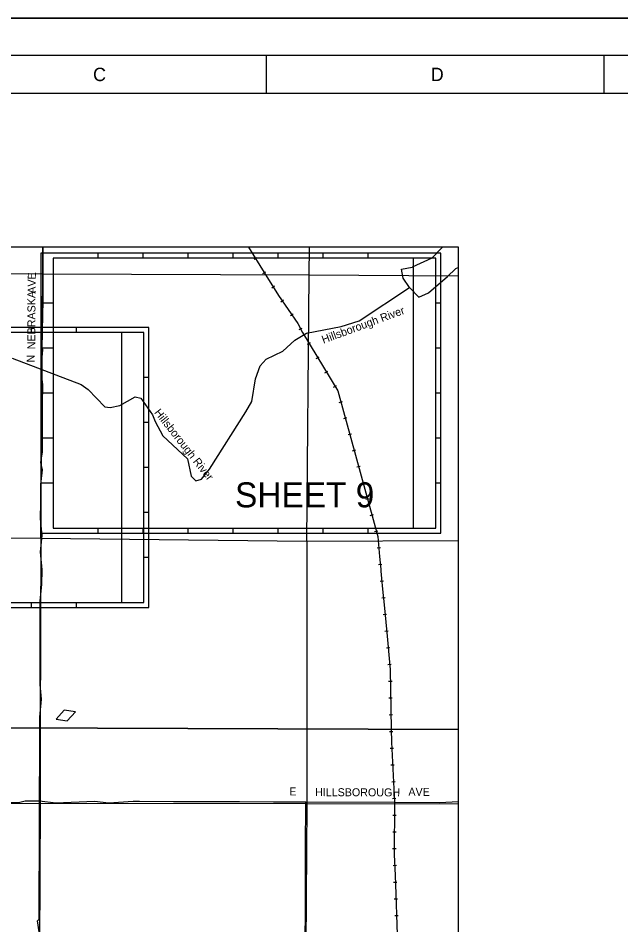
# Model space of a CAD drawing. Extents: x 492225 to 553725, y 1303773 to 1347273.
# Drawn here: x 510130 to 522187, y 1329150 to 1347273 of the extents above; entities that cross this region are included whole.
import ezdxf

# ---------------------------------------------------------------- set-up
doc = ezdxf.new("R2010")
doc.units = 0
for name, color, linetype in [('G-ANNO-TTLB', 7, 'Continuous'), ('Level 1', 7, 'Continuous'), ('Level 13', 7, 'Continuous'), ('Level 19', 7, 'Continuous'), ('Level 22', 7, 'Continuous'), ('Level 37', 7, 'Continuous'), ('Level 41', 7, 'Continuous'), ('Level 5', 7, 'Continuous'), ('Level 52', 7, 'Continuous'), ('Level 63', 7, 'Continuous')]:
    doc.layers.add(name, color=color, linetype=linetype)

msp = doc.modelspace()

# ---------------------------------------------------------------- linework, layer by layer
at = {"layer": 'G-ANNO-TTLB'}
for p, q in [((552975.069, 1346522.564), (492975.069, 1346522.564)), ((515100.069, 1345772.564), (515100.069, 1346522.564)), ((521850.069, 1345772.564), (521850.069, 1346522.564)), ((494850.069, 1345772.564), (552225.069, 1345772.564))]:
    msp.add_line(p, q, dxfattribs=at)
for points in [[(492225.069, 1303772.564), (553725.069, 1303772.564), (553725.069, 1347272.564), (492225.069, 1347272.564)], [(492225.069, 1303772.564), (553725.069, 1303772.564), (553725.069, 1347272.564), (492225.069, 1347272.564)], [(492225.069, 1347272.564), (553725.069, 1347272.564), (553725.069, 1303772.564), (492225.069, 1303772.564)]]:
    msp.add_lwpolyline(points, close=True, dxfattribs=at)
at = {"layer": 'Level 1'}
for p, q in [((510624.879, 1342164.808), (510624.2744, 1342691.84)), ((511733.225, 1342476.88), (511733.225, 1342576.88)), ((512633.225, 1342476.88), (512633.225, 1342576.88)), ((513533.225, 1342476.88), (513533.225, 1342576.88)), ((514433.225, 1342476.88), (514433.225, 1342576.88)), ((515333.225, 1342476.88), (515333.225, 1342576.88)), ((515954.774, 1342144.304), (515956.0062, 1342691.84)), ((516233.225, 1342476.88), (516233.225, 1342576.88)), ((517133.225, 1342476.88), (517133.225, 1342576.88)), ((518033.225, 1342476.88), (518033.225, 1337076.88)), ((505297.021, 1342191.301), (510624.879, 1342164.808)), ((510580.913, 1336869.862), (510624.879, 1342164.808)), ((510624.879, 1342164.808), (515954.774, 1342144.304)), ((515908.569, 1336811.383), (515954.774, 1342144.304)), ((515954.774, 1342144.304), (518939.561, 1342121.5763)), ((510833.225, 1341576.88), (510583.225, 1341576.88)), ((518583.225, 1341576.88), (518483.225, 1341576.88)), ((510395.516, 1340991.129), (510395.516, 1341091.129)), ((511295.516, 1340991.129), (511295.516, 1341091.129)), ((512195.516, 1340991.129), (512195.516, 1335591.129)), ((510833.225, 1340676.88), (510583.225, 1340676.88)), ((518583.225, 1340676.88), (518483.225, 1340676.88)), ((512745.516, 1340091.129), (512645.516, 1340091.129)), ((510833.225, 1339776.88), (510583.225, 1339776.88)), ((518583.225, 1339776.88), (518483.225, 1339776.88)), ((512745.516, 1339191.129), (512645.516, 1339191.129)), ((510833.225, 1338876.88), (510583.225, 1338876.88)), ((518583.225, 1338876.88), (518483.225, 1338876.88)), ((512745.516, 1338291.129), (512645.516, 1338291.129)), ((510833.225, 1337976.88), (510583.225, 1337976.88)), ((518583.225, 1337976.88), (518483.225, 1337976.88)), ((512745.516, 1337391.129), (512645.516, 1337391.129)), ((511733.225, 1336976.88), (511733.225, 1337076.88)), ((512633.225, 1336976.88), (512633.225, 1337076.88)), ((513533.225, 1336976.88), (513533.225, 1337076.88)), ((514433.225, 1336976.88), (514433.225, 1337076.88)), ((515333.225, 1336976.88), (515333.225, 1337076.88)), ((516233.225, 1336976.88), (516233.225, 1337076.88)), ((517133.225, 1336976.88), (517133.225, 1337076.88)), ((510580.913, 1336869.862), (505239.221, 1336922.412)), ((510580.913, 1336869.862), (510573.52, 1333086.244)), ((515908.569, 1336811.383), (510580.913, 1336869.862)), ((515908.569, 1336811.383), (515904.419, 1333067.191)), ((518939.561, 1336824.8508), (515908.569, 1336811.383)), ((512745.516, 1336491.129), (512645.516, 1336491.129)), ((510395.516, 1335491.129), (510395.516, 1335591.129)), ((511295.516, 1335491.129), (511295.516, 1335591.129)), ((510573.52, 1333086.244), (510570.569, 1331572.735)), ((515904.419, 1333067.191), (515902.766, 1331568.651)), ((510570.569, 1331572.735), (505144.045, 1331549.672)), ((510570.569, 1331572.735), (510543.414, 1326261.323)), ((515902.766, 1331568.651), (510570.569, 1331572.735)), ((515902.766, 1331568.651), (515873.149, 1326207.263)), ((518939.561, 1331564.3323), (515902.766, 1331568.651))]:
    msp.add_line(p, q, dxfattribs=at)
for points in [[(510583.225, 1336976.88), (518583.225, 1336976.88), (518583.225, 1342576.88), (510583.225, 1342576.88)], [(510833.225, 1337076.88), (518483.225, 1337076.88), (518483.225, 1342476.88), (510833.225, 1342476.88)], [(504745.516, 1335491.129), (512745.516, 1335491.129), (512745.516, 1341091.129), (504745.516, 1341091.129)], [(504995.516, 1335591.129), (512645.516, 1335591.129), (512645.516, 1340991.129), (504995.516, 1340991.129)]]:
    msp.add_lwpolyline(points, close=True, dxfattribs=at)
at = {"layer": 'Level 13'}
for p, q in [((510631.216, 1342388.123), (510632.159, 1342642.609)), ((510632.159, 1342642.609), (510632.3412, 1342691.84)), ((510630.543, 1342206.348), (510631.216, 1342388.123)), ((510628.793, 1341733.733), (510630.543, 1342206.348)), ((510626.908, 1341224.763), (510628.793, 1341733.733)), ((510593.029, 1340788.621), (510626.908, 1341224.763)), ((510624.754, 1340643.082), (510593.029, 1340788.621)), ((510591.144, 1340279.651), (510624.754, 1340643.082)), ((510590.874, 1340206.94), (510591.144, 1340279.651)), ((510622.197, 1339952.337), (510590.874, 1340206.94)), ((510620.716, 1339552.431), (510622.197, 1339952.337)), ((510620.312, 1339443.367), (510620.716, 1339552.431)), ((510619.37, 1339188.881), (510620.312, 1339443.367)), ((510618.428, 1338934.397), (510619.37, 1339188.881)), ((510617.216, 1338607.201), (510618.428, 1338934.397)), ((510584.143, 1338389.19), (510617.216, 1338607.201)), ((510615.87, 1338243.651), (510584.143, 1338389.19)), ((510582.528, 1337952.931), (510615.87, 1338243.651)), ((510581.181, 1337589.381), (510582.528, 1337952.931)), ((510579.97, 1337262.185), (510581.181, 1337589.381)), ((510611.025, 1336934.873), (510579.97, 1337262.185)), ((510577.548, 1336607.796), (510611.025, 1336934.873)), ((510608.469, 1336244.128), (510577.548, 1336607.796)), ((510607.393, 1335953.288), (510608.469, 1336244.128)), ((510573.914, 1335626.213), (510607.393, 1335953.288)), ((510573.24, 1335444.438), (510573.914, 1335626.213)), ((510572.164, 1335153.598), (510573.24, 1335444.438)), ((510570.953, 1334826.403), (510572.164, 1335153.598)), ((510570.145, 1334608.273), (510570.953, 1334826.403)), ((510568.934, 1334281.079), (510570.145, 1334608.273)), ((510567.723, 1333953.885), (510568.934, 1334281.079)), ((510598.916, 1333662.927), (510567.723, 1333953.885)), ((510565.3, 1333299.497), (510598.916, 1333662.927)), ((510564.512, 1333086.277), (510565.3, 1333299.497)), ((510563.956, 1332935.946), (510564.512, 1333086.277)), ((510562.881, 1332645.104), (510563.956, 1332935.946)), ((510561.537, 1332281.553), (510562.881, 1332645.104)), ((510560.327, 1331954.355), (510561.537, 1332281.553)), ((510559.118, 1331627.158), (510560.327, 1331954.355)), ((509957.453, 1331594.479), (510139.457, 1331592.353)), ((510139.457, 1331592.353), (510268.676, 1331628.23)), ((510268.676, 1331628.23), (510559.118, 1331627.158)), ((510559.118, 1331627.158), (510881.696, 1331589.614)), ((510881.696, 1331589.614), (511656.339, 1331623.127)), ((511656.339, 1331623.127), (511946.647, 1331585.71)), ((511946.647, 1331585.71), (512430.848, 1331620.3)), ((512430.848, 1331620.3), (512559.934, 1331619.831)), ((512559.934, 1331619.831), (513237.629, 1331617.372)), ((513237.629, 1331617.372), (513915.324, 1331614.924)), ((513915.324, 1331614.924), (514560.747, 1331612.604)), ((514560.747, 1331612.604), (515238.443, 1331610.18)), ((515238.443, 1331610.18), (515883.867, 1331607.882)), ((515883.867, 1331607.882), (517658.78, 1331601.617)), ((517658.78, 1331601.617), (518562.374, 1331598.458)), ((518562.374, 1331598.458), (518939.561, 1331617.378))]:
    msp.add_line(p, q, dxfattribs=at)
at = {"layer": 'Level 22'}
for p, q in [((510557.909, 1331299.961), (510559.118, 1331627.158)), ((515882.701, 1331280.686), (515883.867, 1331607.882)), ((510556.699, 1330972.764), (510557.909, 1331299.961)), ((515881.665, 1330989.844), (515882.701, 1331280.686)), ((510556.027, 1330790.988), (510556.699, 1330972.764)), ((515880.5, 1330662.648), (515881.665, 1330989.844)), ((510555.489, 1330645.567), (510556.027, 1330790.988)), ((510554.952, 1330500.146), (510555.489, 1330645.567)), ((515879.206, 1330299.096), (515880.5, 1330662.648)), ((510554.28, 1330318.37), (510554.952, 1330500.146)), ((510553.609, 1330136.594), (510554.28, 1330318.37)), ((515878.299, 1330044.61), (515879.206, 1330299.096)), ((510553.205, 1330027.529), (510553.609, 1330136.594)), ((515877.911, 1329935.544), (515878.299, 1330044.61)), ((510552.534, 1329845.753), (510553.205, 1330027.529)), ((515877.264, 1329753.768), (515877.911, 1329935.544)), ((510551.324, 1329518.556), (510552.534, 1329845.753)), ((515876.875, 1329644.703), (515877.264, 1329753.768)), ((510550.384, 1329264.07), (510551.324, 1329518.556)), ((515876.228, 1329462.928), (515876.875, 1329644.703)), ((515875.711, 1329317.507), (515876.228, 1329462.928)), ((510517.976, 1329227.833), (510550.384, 1329264.07)), ((510549.443, 1329009.583), (510517.976, 1329227.833)), ((515874.417, 1328953.955), (515875.711, 1329317.507))]:
    msp.add_line(p, q, dxfattribs=at)
at = {"layer": 'Level 37'}
for p, q in [((514849.334, 1342452.582), (514906.664, 1342487.91)), ((515025.163, 1342167.329), (515082.241, 1342203.063)), ((515202.85, 1341883.513), (515259.929, 1341919.248)), ((515386.231, 1341601.678), (515441.698, 1341639.868)), ((515576.129, 1341325.881), (515631.594, 1341364.072)), ((515751.719, 1341046.037), (515811.272, 1341077.475)), ((515921.814, 1340755.445), (515979.425, 1340790.314)), ((516095.202, 1340468.98), (516152.813, 1340503.85)), ((516268.588, 1340182.516), (516326.199, 1340217.386)), ((516441.974, 1339896.052), (516499.585, 1339930.922)), ((516553.833, 1339593.292), (516618.789, 1339611.06)), ((516642.182, 1339270.306), (516707.137, 1339288.074)), ((516730.531, 1338947.321), (516795.486, 1338965.089)), ((516818.88, 1338624.336), (516883.834, 1338642.104)), ((516907.229, 1338301.35), (516972.184, 1338319.119)), ((516995.578, 1337978.366), (517060.534, 1337996.133)), ((517083.927, 1337655.38), (517148.882, 1337673.149)), ((517172.275, 1337332.394), (517237.231, 1337350.163)), ((517260.624, 1337009.41), (517325.579, 1337027.178)), ((517309.926, 1336685.224), (517376.972, 1336691.532)), ((517341.286, 1336351.844), (517408.332, 1336358.153)), ((517372.327, 1336018.435), (517439.372, 1336024.743)), ((517403.639, 1335685.061), (517470.686, 1335691.35)), ((517434.839, 1335351.678), (517501.889, 1335357.944)), ((517465.994, 1335018.279), (517533.044, 1335024.546)), ((517497.257, 1334684.878), (517564.303, 1334691.168)), ((517528.528, 1334351.491), (517595.574, 1334357.781)), ((517542.047, 1334019.629), (517609.377, 1334020.887)), ((517548.296, 1333684.836), (517615.625, 1333686.094)), ((517554.544, 1333350.043), (517621.874, 1333351.301)), ((517560.794, 1333015.249), (517628.123, 1333016.508)), ((517570.881, 1332679.521), (517638.138, 1332682.903)), ((517587.694, 1332345.089), (517654.949, 1332348.47)), ((517604.505, 1332010.656), (517671.761, 1332014.038)), ((517621.317, 1331676.223), (517688.574, 1331679.604)), ((517624.201, 1331343.273), (517691.543, 1331343.038)), ((517623.024, 1331008.421), (517690.365, 1331008.184)), ((517621.848, 1330673.568), (517689.188, 1330673.332)), ((517629.157, 1330337.491), (517696.451, 1330339.985)), ((517641.516, 1330002.868), (517708.812, 1330005.353)), ((517653.819, 1329668.244), (517721.115, 1329670.718)), ((517666.115, 1329333.616), (517733.41, 1329336.089))]:
    msp.add_line(p, q, dxfattribs=at)
for points in [[(514741.4486, 1342691.84), (515050.523, 1342190.275), (515337.953, 1341731.168), (515724.398, 1341169.917), (515820.539, 1340987.797), (516526.202, 1339821.919), (517322.538, 1336910.682), (517360.168, 1336510.641), (517384.114, 1336256.07), (517387.529, 1336217.885), (517400.897, 1336074.235), (517421.424, 1335856.031), (517450.344, 1335547.637), (517502.273, 1334991.945), (517571.314, 1334255.872), (517593.613, 1333061.154)], [(517593.613, 1333061.154), (517598.459, 1332801.564), (517658.78, 1331601.617), (517655.074, 1330547.317), (517664.507, 1330292.795), (517676.588, 1329965.552), (517713.997, 1328947.464)]]:
    msp.add_lwpolyline(points, dxfattribs=at)
at = {"layer": 'Level 5'}
msp.add_line((518405.346, 1342476.771), (518013.076, 1342294.618), dxfattribs=at)
for points in [[(518621.7187, 1342691.84), (518405.346, 1342476.771)], [(517961.794, 1341886.391), (517829.065, 1342078.508), (517796.256, 1342253.627), (518013.076, 1342294.618)], [(518939.561, 1342290.0149), (518879.744, 1342258.646), (518720.904, 1342109.096)], [(517961.794, 1341886.391), (518144.563, 1341694.163), (518336.523, 1341785.254), (518720.904, 1342109.096)], [(510009.667, 1340474.192), (511388.39, 1339947.934), (511529.789, 1339847.506), (511862.108, 1339504.781), (511970.398, 1339487.782), (512162.217, 1339528.863), (512471.107, 1339702.945), (512587.696, 1339677.587), (512820.035, 1339343.49), (512869.654, 1339209.992), (513027.124, 1338926.134), (513517.45, 1338466.252), (513591.359, 1338115.984), (513682.779, 1338024.036), (513799.549, 1338057.027), (513958.499, 1338256.547), (514687.131, 1339404.457), (514804.431, 1339612.437), (514880.843, 1340062.285), (514973.294, 1340320.364), (515090.404, 1340453.324), (515424.264, 1340619.017), (515666.624, 1340834.948), (515900.444, 1340975.928), (516592.584, 1341107.154), (516951.303, 1341222.747), (517961.794, 1341886.391)], [(511275.639, 1333405.949), (511049.885, 1333443.134), (510887.865, 1333261.953), (511113.62, 1333224.768), (511275.639, 1333405.949)]]:
    msp.add_lwpolyline(points, dxfattribs=at)
at = {"layer": 'Level 52'}
msp.add_lwpolyline([(518939.5614, 1342691.8404), (495463.7934, 1342691.8404), (495463.7934, 1307817.676), (518939.5614, 1307817.676)], close=True, dxfattribs=at)
at = {"layer": 'Level 63'}
for points in [[(518939.561, 1333056.3431), (495463.793, 1333140.2488)], [(495463.793, 1333140.2488), (518939.561, 1333056.3431)]]:
    msp.add_lwpolyline(points, dxfattribs=at)

# ---------------------------------------------------------------- texts
at = {"layer": 'G-ANNO-TTLB'}
for s, p in [('C', (511629.069, 1346014.064)), ('D', (518385.069, 1346014.064))]:
    msp.add_text(s, height=267.507, dxfattribs=at).set_placement(p)
at = {"layer": 'Level 1'}
msp.add_text('SHEET 9', height=500, dxfattribs=at).set_placement((514468.852, 1337494.519))
at = {"layer": 'Level 19'}
for s, height, rotation, p in [('AVE', 160, 89.78800002, (510482.886, 1341764.601)), ('NEBRASKA', 160, 89.78800002, (510473.361, 1340653.33)), ('N', 160, 89.78800002, (510458.314, 1340388.518)), ('E', 160, 359.7971, (515555.052, 1331736.93)), ('HILLSBOROUGH', 159.999996, 359.7971, (516069.469, 1331722.59)), ('AVE', 160, 359.7971, (517936.755, 1331729.068))]:
    msp.add_text(s, height=height, rotation=rotation, dxfattribs=at).set_placement(p)
at = {"layer": 'Level 41'}
for rotation, p in [(20.22041389, (516236.888, 1340764.727)), (308.33432781, (512844.173, 1339386.163))]:
    msp.add_text('Hillsborough River', height=159.999996, rotation=rotation, dxfattribs=at).set_placement(p)

doc.saveas('drawing.dxf')
